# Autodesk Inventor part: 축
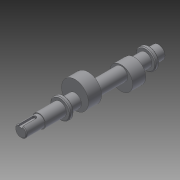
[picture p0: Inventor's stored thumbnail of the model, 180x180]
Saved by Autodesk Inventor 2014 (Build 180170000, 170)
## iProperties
Created: 2014-12
Part Number: 축
Material: 일반
Document SubType Name: Modeling
Designer: Owner
Density: 1 g/cm^3
Appearance: 기본값
Mass: 62.8614 g
Surface Area: 153.402 cm^2
Volume: 62.8614 cm^3
Author: Owner
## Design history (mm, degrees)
sketch "스케치1"
  geometry: L1 (-90, 0)-(90, 0); L2 (-90, 0)-(-90, 7.5); L3 (-90, 7.5)-(-66, 7.5); L4 (-66, 7.5)-(-66, 8.5); L5 (-66, 8.5)-(-39, 8.5); L6 (-39, 8.5)-(-39, 13); L7 (-39, 13)-(-34, 13); L8 (-34, 13)-(-34, 8.5); L9 (72, 8.5)-(72, 13); L10 (72, 13)-(77, 13); L11 (77, 13)-(77, 8.5); L12 (77, 8.5)-(90, 8.5); L13 (90, 8.5)-(90, 0); L14 (-34, 8.5)-(72, 8.5); 2 further points
  constraints: 28 end point, 10 parallel, 3 perpendicular, 1 coincident, 1 horizontal, 1 horizontal alignment, 1 midpoint
  dimensions: "d0" = 180 distance of L1.start L1.end; "d2" = 15 diameter of L3 L1; "d3" = 17 diameter of L5 L1; "d4" = 26 diameter of L7 L1; "d5" = 24 distance of L2.end L3.end; "d6" = 27 distance of L4.end L5.end; "d7" = 5 distance of L6.end L7.end; "d8" = 13 distance of L11.end L12.end; "d9" = 5 distance of L9.end L10.end; "d10" = 17 diameter of L12 L1; "d11" = 26 diameter of L10 L1
revolve "회전1" sketch "스케치1" stored, may be unused: angle "d14" = 90 deg
node "작업 평면2"
sketch "스케치2"
  geometry: C1 r 17.5 at (0, 6); 1 further point
  constraints: 1 centre point, 1 vertical alignment
  dimensions: "d16" = 35 diameter of C1; "d17" = 6 distance of point (0, 0) C1.centre
extrude "돌출1" join sketch "스케치2" distance "d18" = 17; taper "d19" = 0 deg
node "작업 평면3"
sketch "스케치3"
  geometry: C1 r 15 at (0, -5); 1 further point
  constraints: 1 centre point, 1 vertical alignment
  dimensions: "d23" = 30 diameter of C1; "d24" = 5 distance of C1.centre point (0, 0)
extrude "돌출2" join sketch "스케치3" distance "d25" = 17; taper "d26" = 0 deg
node "작업 평면4"
sketch "스케치4"
  geometry: L1 (5.5, 0)-(-14.5, 0); L2 (5.5, 2.5)-(-14.5, 2.5); L3 (-14.5, -2.5)-(5.5, -2.5); L4 (-12, -7.5)-(-12, 7.5) reference; A1 r 2.5 centre (5.5, 0) between (5.5, -2.5) and (5.5, 2.5); A2 r 2.5 centre (-14.5, 0) between (-14.5, 2.5) and (-14.5, -2.5); 2 further points
  constraints: 8 end point, 4 point on circle, 4 tangent, 2 centre point, 1 horizontal, 1 horizontal alignment, 1 midpoint, 1 parallel
  dimensions: "d27" = 20 dimension on A1 L4; "d28" = 5 distance between parallel lines of L3 L2; "d29" = 20 distance of L3.start L3.end
chamfer "모따기1" distance "d30" = 1; stored, may be unused: second distance "d31" = 2, angle "d32" = 45 deg
extrude "돌출3" cut sketch "스케치4" distance "d33" = 3; taper "d34" = 0 deg
node "솔리드1"
other parameters: "d15" = 14.5, "d20" = 14.5
